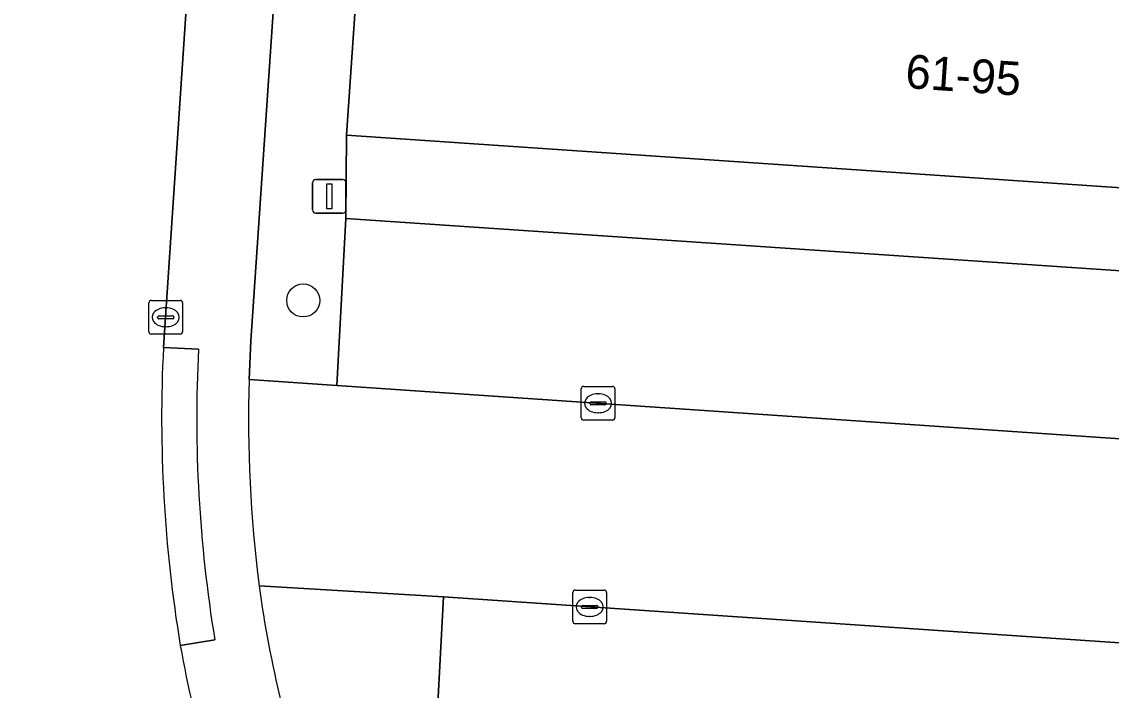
# Model space of a CAD drawing. Extents: x 159960 to 160866, y 382700 to 383354.
# Drawn here: x 160569.3 to 160601.59, y 382766.97 to 382786.78 of the extents above; entities that cross this region are included whole.
import ezdxf

# ---------------------------------------------------------------- set-up
doc = ezdxf.new("R2010")
doc.units = 0
for name, color, linetype in [('IMGEO_Boom', 7, 'Continuous'), ('IMGEO_Groenvoorziening', 7, 'Continuous'), ('IMGEO_Kolk', 7, 'Continuous'), ('IMGEO_Lichtmast', 7, 'Continuous'), ('IMGEO_Pand', 7, 'Continuous'), ('IMGEO_Pand_nummerreeks', 7, 'Continuous'), ('IMGEO_Parkeervlak_open', 7, 'Continuous'), ('IMGEO_Rijbaan_lokaal_open', 7, 'Continuous'), ('IMGEO_Voetpad_open', 7, 'Continuous')]:
    doc.layers.add(name, color=color, linetype=linetype)

msp = doc.modelspace()

# ---------------------------------------------------------------- linework, layer by layer
at = {"layer": 'IMGEO_Boom'}
msp.add_circle((160577.641, 382778.517), 0.489, dxfattribs=at)
at = {"layer": 'IMGEO_Groenvoorziening'}
msp.add_lwpolyline([(160581.767, 382756.083), (160586.4, 382749.149), (160586.848, 382748.497), (160593.244, 382751.503), (160586.996, 382760.857), (160581.346, 382761.226), (160581.532, 382764.721), (160581.798, 382769.731), (160576.335, 382770.065)], dxfattribs=at)
msp.add_arc((160608.939, 382774.446), 32.897, 187.6532, 199.8215, dxfattribs=at)
at = {"layer": 'IMGEO_Kolk'}
for p, q in [((160573.066, 382777.593), (160573.066, 382778.445)), ((160573.141, 382778.519), (160573.993, 382778.519)), ((160573.554, 382778.299), (160573.579, 382778.299)), ((160574.067, 382778.445), (160574.067, 382777.593)), ((160573.325, 382778.013), (160573.325, 382778.025)), ((160573.763, 382777.976), (160573.365, 382777.976)), ((160573.368, 382778.062), (160573.766, 382778.062)), ((160573.809, 382778.025), (160573.809, 382778.013)), ((160573.577, 382777.739), (160573.552, 382777.739)), ((160573.993, 382777.519), (160573.141, 382777.519)), ((160585.88, 382775.045), (160585.88, 382775.897)), ((160585.955, 382775.971), (160586.807, 382775.971)), ((160586.368, 382775.751), (160586.393, 382775.751)), ((160586.881, 382775.897), (160586.881, 382775.045)), ((160586.139, 382775.465), (160586.139, 382775.477)), ((160586.577, 382775.428), (160586.179, 382775.428)), ((160586.182, 382775.514), (160586.58, 382775.514)), ((160586.623, 382775.477), (160586.623, 382775.465)), ((160586.391, 382775.191), (160586.366, 382775.191)), ((160586.807, 382774.971), (160585.955, 382774.971)), ((160585.631, 382769.01), (160585.631, 382769.862)), ((160585.706, 382769.936), (160586.558, 382769.936)), ((160586.632, 382769.862), (160586.632, 382769.01)), ((160586.119, 382769.716), (160586.144, 382769.716)), ((160585.89, 382769.43), (160585.89, 382769.442)), ((160586.328, 382769.393), (160585.93, 382769.393)), ((160585.933, 382769.479), (160586.331, 382769.479)), ((160586.374, 382769.442), (160586.374, 382769.43)), ((160586.558, 382768.936), (160585.706, 382768.936)), ((160586.142, 382769.156), (160586.117, 382769.156))]:
    msp.add_line(p, q, dxfattribs=at)
for points in [[(160573.066, 382777.593), (160573.066, 382778.445)], [(160573.141, 382778.519), (160573.993, 382778.519)], [(160574.067, 382778.445), (160574.067, 382777.593)], [(160573.993, 382777.519), (160573.141, 382777.519)], [(160585.88, 382775.045), (160585.88, 382775.897)], [(160585.955, 382775.971), (160586.807, 382775.971)], [(160586.881, 382775.897), (160586.881, 382775.045)], [(160586.807, 382774.971), (160585.955, 382774.971)], [(160585.631, 382769.01), (160585.631, 382769.862)], [(160585.706, 382769.936), (160586.558, 382769.936)], [(160586.632, 382769.862), (160586.632, 382769.01)], [(160586.558, 382768.936), (160585.706, 382768.936)]]:
    msp.add_lwpolyline(points, dxfattribs=at)
for centre, radius, start, end in [((160573.143, 382778.443), 0.0765, 91.552, 178.448), ((160573.143, 382778.443), 0.0765, 91.552, 178.448), ((160573.991, 382778.443), 0.0765, 1.552, 88.448), ((160573.991, 382778.443), 0.0765, 1.552, 88.448), ((160573.365, 382778.022), 0.0403, 85.8775, 175.7526), ((160573.362, 382778.012), 0.0366, 178.938, 274.7102), ((160573.766, 382778.019), 0.043, 264.8664, 352.4533), ((160573.77, 382778.024), 0.0386, 1.7309, 96.639), ((160573.143, 382777.595), 0.0765, 181.552, 268.448), ((160573.143, 382777.595), 0.0765, 181.552, 268.448), ((160573.991, 382777.595), 0.0765, 271.552, 358.448), ((160573.991, 382777.595), 0.0765, 271.552, 358.448), ((160585.957, 382775.895), 0.0765, 91.552, 178.448), ((160585.957, 382775.895), 0.0765, 91.552, 178.448), ((160586.805, 382775.895), 0.0765, 1.552, 88.448), ((160586.805, 382775.895), 0.0765, 1.552, 88.448), ((160586.179, 382775.474), 0.0403, 85.8775, 175.7526), ((160586.176, 382775.464), 0.0366, 178.938, 274.7102), ((160586.58, 382775.471), 0.043, 264.8664, 352.4533), ((160586.584, 382775.476), 0.0386, 1.7309, 96.639), ((160585.957, 382775.047), 0.0765, 181.552, 268.448), ((160585.957, 382775.047), 0.0765, 181.552, 268.448), ((160586.805, 382775.047), 0.0765, 271.552, 358.448), ((160586.805, 382775.047), 0.0765, 271.552, 358.448), ((160585.708, 382769.86), 0.0765, 91.552, 178.448), ((160585.708, 382769.86), 0.0765, 91.552, 178.448), ((160586.556, 382769.86), 0.0765, 1.552, 88.448), ((160586.556, 382769.86), 0.0765, 1.552, 88.448), ((160585.93, 382769.439), 0.0403, 85.8775, 175.7526), ((160585.927, 382769.429), 0.0366, 178.938, 274.7102), ((160586.331, 382769.436), 0.043, 264.8664, 352.4533), ((160586.335, 382769.441), 0.0386, 1.7309, 96.639), ((160585.708, 382769.012), 0.0765, 181.552, 268.448), ((160585.708, 382769.012), 0.0765, 181.552, 268.448), ((160586.556, 382769.012), 0.0765, 271.552, 358.448), ((160586.556, 382769.012), 0.0765, 271.552, 358.448)]:
    msp.add_arc(centre, radius, start, end, dxfattribs=at)
for centre, major_axis, ratio, start_param, end_param in [((160573.553, 382778.019), (-0.387, 0.002), 0.722429, 4.712389, 7.853982), ((160573.578, 382778.019), (-0.39, 0.002), 0.717154, 1.570796, 4.712389), ((160586.367, 382775.471), (-0.387, 0.002), 0.722429, 4.712389, 7.853982), ((160586.392, 382775.471), (-0.39, 0.002), 0.717154, 1.570796, 4.712389), ((160586.118, 382769.436), (-0.387, 0.002), 0.722429, 4.712389, 7.853982), ((160586.143, 382769.436), (-0.39, 0.002), 0.717154, 1.570796, 4.712389)]:
    msp.add_ellipse(centre, major_axis=major_axis, ratio=ratio, start_param=start_param, end_param=end_param, dxfattribs=at)
at = {"layer": 'IMGEO_Lichtmast'}
for p, q in [((160577.919, 382781.204), (160577.919, 382782.004)), ((160577.919, 382782.004), (160577.919, 382781.204)), ((160578.019, 382782.104), (160578.809, 382782.104)), ((160578.809, 382782.104), (160578.019, 382782.104)), ((160578.909, 382782.004), (160578.909, 382781.204)), ((160578.909, 382781.204), (160578.909, 382782.004)), ((160578.809, 382781.104), (160578.019, 382781.104)), ((160578.019, 382781.104), (160578.809, 382781.104))]:
    msp.add_line(p, q, dxfattribs=at)
msp.add_lwpolyline([(160578.339, 382781.979), (160578.489, 382781.979), (160578.489, 382781.229), (160578.339, 382781.229), (160578.339, 382781.979)], dxfattribs=at)
for centre, start, end in [((160578.019, 382782.004), 90, 180), ((160578.019, 382782.004), 90, 180), ((160578.809, 382782.004), 0, 90), ((160578.809, 382782.004), 360, 90), ((160578.019, 382781.204), 180, 270), ((160578.019, 382781.204), 180, 270), ((160578.809, 382781.204), 270, 0), ((160578.809, 382781.204), 270, 0)]:
    msp.add_arc(centre, 0.1, start, end, dxfattribs=at)
at = {"layer": 'IMGEO_Pand'}
msp.add_lwpolyline([(160617.544, 382791.095), (160617.654, 382792.681), (160617.756, 382794.157), (160617.762, 382794.24), (160604.791, 382795.112), (160579.841, 382796.788), (160578.923, 382783.416), (160616.134, 382780.884), (160616.832, 382780.837), (160616.943, 382782.431), (160617.012, 382783.427), (160617.153, 382785.461), (160617.258, 382786.971), (160617.338, 382788.13), (160617.416, 382789.255)], close=True, dxfattribs=at)
at = {"layer": 'IMGEO_Parkeervlak_open'}
for points in [[(160615.499, 382773.485), (160615.775, 382778.458), (160578.903, 382780.946), (160578.637, 382775.998)], [(160608.662, 382767.91), (160581.798, 382769.731), (160581.532, 382764.721), (160599.882, 382763.523), (160608.364, 382762.969)]]:
    msp.add_lwpolyline(points, close=True, dxfattribs=at)
msp.add_arc((160611.897, 382775.113), 44.514, 174.7261, 198.8383, dxfattribs=at)
at = {"layer": 'IMGEO_Rijbaan_lokaal_open'}
for points in [[(160573.499, 382777.128), (160573.562, 382778.019), (160574.526, 382792.469), (160574.875, 382797.051), (160568.877, 382797.482), (160568.692, 382794.467), (160568.611, 382793.294), (160567.572, 382779.205)], [(160576.335, 382770.065), (160581.798, 382769.731), (160608.662, 382767.91), (160615.196, 382767.531), (160615.499, 382773.485), (160578.637, 382775.998), (160576.041, 382776.175)]]:
    msp.add_lwpolyline(points, dxfattribs=at)
for centre, radius, start, end in [((160611.897, 382775.113), 44.514, 174.7261, 198.8383), ((160614.775, 382775.025), 41.329, 177.0837, 189.3708), ((160614.691, 382774.973), 38.669, 178.2182, 187.2914), ((160607.961, 382774.377), 34.504, 190.1507, 202.6884)]:
    msp.add_arc(centre, radius, start, end, dxfattribs=at)
at = {"layer": 'IMGEO_Voetpad_open'}
for points in [[(160576.041, 382776.175), (160576.094, 382777.321), (160577.996, 382805.387), (160578.329, 382810.169), (160578.481, 382812.352), (160578.565, 382813.832), (160579.697, 382815.478), (160577.619, 382816.909), (160576.459, 382815.284)], [(160576.064, 382814.202), (160575.97, 382812.934), (160575.876, 382811.709), (160574.875, 382797.051), (160574.526, 382792.469), (160573.562, 382778.019), (160573.499, 382777.128), (160574.538, 382777.075)], [(160610.684, 382803.416), (160608.917, 382803.527), (160608.251, 382803.421), (160605.271, 382803.603), (160585.832, 382804.854), (160585.119, 382804.903), (160577.996, 382805.387), (160576.094, 382777.321), (160576.041, 382776.175), (160578.637, 382775.998), (160578.903, 382780.946), (160578.923, 382783.416), (160579.841, 382796.788), (160579.012, 382796.875), (160579.302, 382801.634)], [(160574.538, 382777.075), (160573.499, 382777.128)], [(160573.997, 382768.296), (160575.023, 382768.465)], [(160575.023, 382768.465), (160573.997, 382768.296)]]:
    msp.add_lwpolyline(points, dxfattribs=at)
msp.add_lwpolyline([(160578.923, 382783.416), (160578.903, 382780.946), (160615.775, 382778.458), (160617.87, 382778.334), (160618.011, 382780.729), (160617.99, 382780.73), (160616.832, 382780.837), (160616.134, 382780.884)], close=True, dxfattribs=at)
for centre, radius, start, end in [((160614.775, 382775.025), 41.329, 177.0837, 189.3708), ((160614.693, 382775.018), 40.208, 177.0679, 189.3802), ((160614.693, 382775.018), 40.208, 177.0679, 189.3802), ((160614.691, 382774.973), 38.669, 178.2182, 187.2914), ((160608.939, 382774.446), 32.897, 187.6532, 199.8215), ((160607.961, 382774.377), 34.504, 190.1507, 202.6884)]:
    msp.add_arc(centre, radius, start, end, dxfattribs=at)

# ---------------------------------------------------------------- texts
at = {"layer": 'IMGEO_Pand_nummerreeks'}
msp.add_text('61-95', height=1, rotation=356.1096, dxfattribs=at).set_placement((160595.469, 382784.816))

doc.saveas('drawing.dxf')
